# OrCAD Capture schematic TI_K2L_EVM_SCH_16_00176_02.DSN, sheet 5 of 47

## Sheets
5 PAGE29 : K2L_BMC: size C; title: BMC Processor (LM3S2D93), switches, DIPsw, UART Rx Mux, LEDs
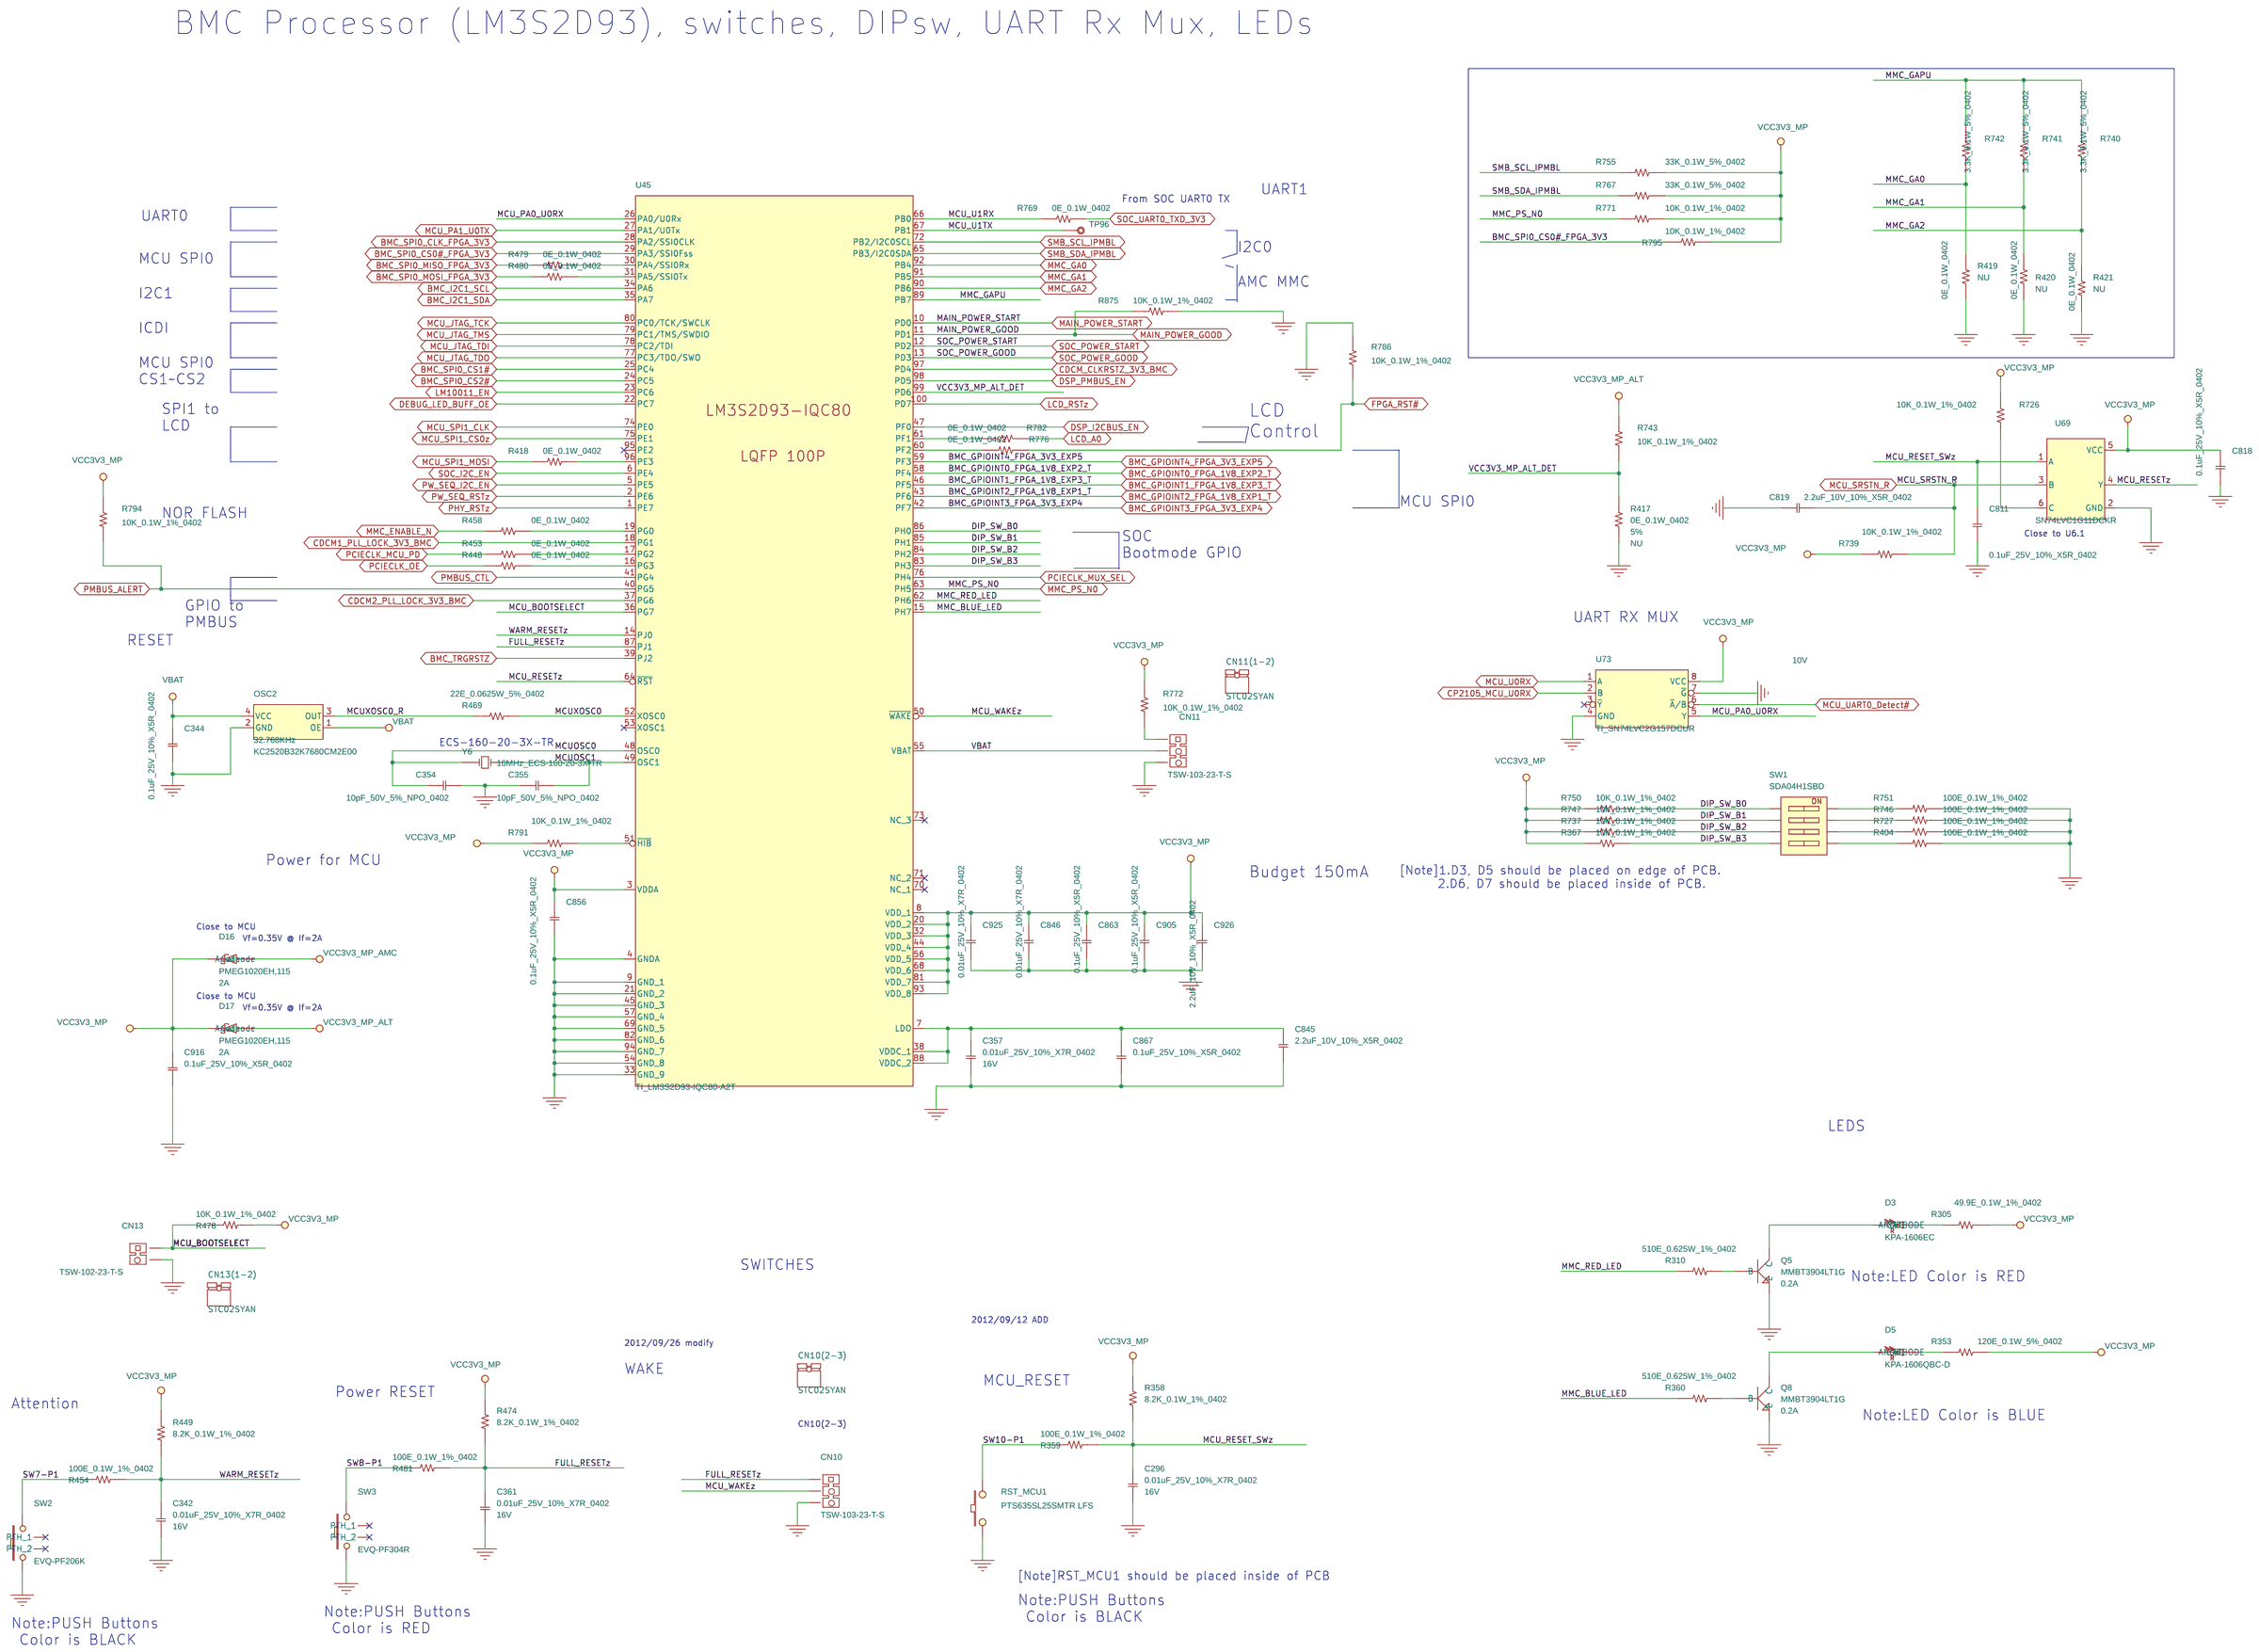
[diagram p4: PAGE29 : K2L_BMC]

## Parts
C296  0.01uF_25V_10%_X7R_0402  [C0402]
C342  0.01uF_25V_10%_X7R_0402  [C0402]
C344  0.1uF_25V_10%_X5R_0402  [C0402]
C354  10pF_50V_5%_NPO_0402  [C0402]
C355  10pF_50V_5%_NPO_0402  [C0402]
C357  0.01uF_25V_10%_X7R_0402  [C0402]
C361  0.01uF_25V_10%_X7R_0402  [C0402]
C811  0.1uF_25V_10%_X5R_0402  [C0402]
C818  0.1uF_25V_10%_X5R_0402  [C0402]
C819  2.2uF_10V_10%_X5R_0402  [C0402]
C845  2.2uF_10V_10%_X5R_0402  [C0402]
C846  0.01uF_25V_10%_X7R_0402  [C0402]
C856  0.1uF_25V_10%_X5R_0402  [C0402]
C863  0.1uF_25V_10%_X5R_0402  [C0402]
C867  0.1uF_25V_10%_X5R_0402  [C0402]
C905  0.1uF_25V_10%_X5R_0402  [C0402]
C916  0.1uF_25V_10%_X5R_0402  [C0402]
C925  0.01uF_25V_10%_X7R_0402  [C0402]
C926  2.2uF_10V_10%_X5R_0402  [C0402]
CN10  TSW-103-23-T-S  [BERG_1X3]
CN10(2-3)  STC02SYAN  [NA]
CN11  TSW-103-23-T-S  [BERG_1X3]
CN11(1-2)  STC02SYAN  [NA]
CN13  TSW-102-23-T-S  [SAMTSW-102-22-T-S]
CN13(1-2)  STC02SYAN  [NA]
D3  KPA-1606EC  [LED_2P_KPA-1606EC]
D5  KPA-1606QBC-D  [LED_2P_KPA-1606QBC-D]
D16  PMEG1020EH,115  [DIODE_2P_146_106x61_ANODE2]
D17  PMEG1020EH,115  [DIODE_2P_146_106x61_ANODE2]
OSC2  32.768KHz  [OSCCC200X250X70-4N]
Q5  MMBT3904LT1G  [SOT-23]
Q8  MMBT3904LT1G  [SOT-23]
R305  49.9E_0.1W_1%_0402  [R0402]
R310  510E_0.625W_1%_0402  [R0402]
R353  120E_0.1W_5%_0402  [R0402]
R358  8.2K_0.1W_1%_0402  [R0402]
R359  100E_0.1W_1%_0402  [R0402]
R360  510E_0.625W_1%_0402  [R0402]
R367  10K_0.1W_1%_0402  [R0402]
R404  100E_0.1W_1%_0402  [R0402]
R417  0E_0.1W_0402  [R0402]
R418  0E_0.1W_0402  [R0402]
R419  0E_0.1W_0402  [R0402]
R420  0E_0.1W_0402  [R0402]
R421  0E_0.1W_0402  [R0402]
R448  0E_0.1W_0402  [R0402]
R449  8.2K_0.1W_1%_0402  [R0402]
R453  0E_0.1W_0402  [R0402]
R454  100E_0.1W_1%_0402  [R0402]
R458  0E_0.1W_0402  [R0402]
R469  22E_0.0625W_5%_0402  [R0402]
R474  8.2K_0.1W_1%_0402  [R0402]
R478  10K_0.1W_1%_0402  [R0402]
R479  0E_0.1W_0402  [R0402]
R480  0E_0.1W_0402  [R0402]
R481  100E_0.1W_1%_0402  [R0402]
R726  10K_0.1W_1%_0402  [R0402]
R727  100E_0.1W_1%_0402  [R0402]
R737  10K_0.1W_1%_0402  [R0402]
R739  10K_0.1W_1%_0402  [R0402]
R740  3.3K_0.1W_5%_0402  [R0402]
R741  3.3K_0.1W_5%_0402  [R0402]
R742  3.3K_0.1W_5%_0402  [R0402]
R743  10K_0.1W_1%_0402  [R0402]
R746  100E_0.1W_1%_0402  [R0402]
R747  10K_0.1W_1%_0402  [R0402]
R750  10K_0.1W_1%_0402  [R0402]
R751  100E_0.1W_1%_0402  [R0402]
R755  33K_0.1W_5%_0402  [R0402]
R767  33K_0.1W_5%_0402  [R0402]
R769  0E_0.1W_0402  [R0402]
R771  10K_0.1W_1%_0402  [R0402]
R772  10K_0.1W_1%_0402  [R0402]
R776  0E_0.1W_0402  [R0402]
R782  0E_0.1W_0402  [R0402]
R786  10K_0.1W_1%_0402  [R0402]
R791  10K_0.1W_1%_0402  [R0402]
R794  10K_0.1W_1%_0402  [R0402]
R795  10K_0.1W_1%_0402  [R0402]
R875  10K_0.1W_1%_0402  [R0402]
RST_MCU1  PTS635SL25SMTR LFS  [SW_PTS635SL25SMTRLFS]
SW1  SDA04H1SBD  [SW_SDA04H1SBD]
SW2  EVQ-PF206K  [SW_EVQ-PF206K]
SW3  EVQ-PF304R  [SW_EVQ-PF104R]
TP96  TP  [TP-S40]
U45  TI_LM3S2D93-IQC80-A2T  [QFP_100P_20_630x630]
U69  SN74LVC1G11DCKR  [SC70_6p]
U73  TI_SN74LVC2G157DCUR  [SOIC_8P_20_79X122]
Y6  16MHz_ECS-160-20-3X-TR  [XTAL_ECS-120-20-3X-TR]

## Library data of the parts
C296 C342 C357 C846 C925 = 11_C_0: CAP CER 10000PF 25V 10% X7R 0402; Advansus_Part_Number: 11G232110312030; Characteristic: 16V; Distributor_name: DIGIKEY; Distributor_part_number: 445-1260-1-ND; EIC Part#: 03_00029_04; GROUP: CPU1; Manufacture: TDK Corporation; Manufacture Part Number: C1005X7R1E103K; Manufacture(English): TDK Corporation; Manufacture_Part_Number: C1005X7R1E103K; Manufacturer: TDK Corporation; Manufacturer_Part_No: C1005X7R1E103K; Mfg: TDK Corporation; Mfg Part#: 03_00029_04; Mfr_name: TDK Corporation; Mfr_part_number: C1005X7R1E103K; Package: 0402; Part_Number: 1121610790; Price @ 1: 0.10000; Price @ 10K: 0.00420; Price @ 1K: 0.00600; ProcessType: SMT; ROOM: CPU1; Tolerance: 10%; Vendor: DIGIKEY; Vendor_Part_No: 445-1260-1-ND; eI Part#: 03_00029_04
C344 C856 C863 C867 C905 = 11_C_0: CAP CER 0.1UF 25V 10% X5R 0402; Avalue_Part_Number: E1123510400H; Distributor_name: DIGIKEY; Distributor_part_number: 445-4964-1-ND; EIC Part#: 03_00470_02; MOUNTED: <MOUNTED>; Manufacture: TDK Corporation; Manufacture Part Number: C1005X5R1E104K050BC; Manufacture(English): TDK Corporation; Manufacture_Part_Number: GRM155R71C104KA88D; Manufacturer: TDK Corporation; Manufacturer_Part_No: C1005X5R1E104K050BC; Mfg: Murata Electronics North America; Mfg Part#: 03_00470_02; Mfr_name: TDK Corporation; Mfr_part_number: C1005X5R1E104K050BC; Package: 0402; Price @ 1: 0.10000; Price @ 1K: 0.00420; ProcessType: SMT; Tolerance: 10%; Vendor: DIGIKEY; Vendor Part#: 445-4964-1-ND; Vendor_Part_No: 445-4964-1-ND; eI Part#: 03_00470_02
C354 C355 = 11_C_0: CAP CER 10PF 50V 5% NPO 0402; Advansus_Part_Number: 11G232010004030; Characteristic: 50V; Distributor_name: DIGIKEY; Distributor_part_number: 490-5921-6-ND; EIC Part#: 03_00366_03; Manufacture: Murata; Manufacture Part Number: GRM1555C1H100JA01D; Manufacture(English): Murata; Manufacture_Part_Number: CC0402JRNPO9BN100; Manufacturer: Murata; Manufacturer_Part_No: GRM1555C1H100JA01D; Mfg: Yageo; Mfg Part#: 03_00366_03; Mfr_name: Murata; Mfr_part_number: GRM1555C1H100JA01D; Package: 0402; Part_Number: 1124410091; Price @ 1: 0.10000; Price @ 10K: 0.00227; Price @ 1K: 0.00324; ProcessType: SMT; Tolerance: 5%; Vendor: DIGIKEY; Vendor_Part_No: 490-5921-6-ND; eI Part#: 03_00366_03
C361 = 11_C_0: CAP CER 10000PF 25V 10% X7R 0402; Advansus_Part_Number: 11G232110312030; Characteristic: 16V; Distributor_name: DIGIKEY; Distributor_part_number: 445-1260-1-ND; EIC Part#: 03_00029_04; GROUP: CPU1; Manufacture: TDK Corporation; Manufacture Part Number: C1005X7R1E103K; Manufacture(English): TDK Corporation; Manufacture_Part_Number: C1005X7R1E103K; Manufacturer: TDK Corporation; Manufacturer_Part_No: C1005X7R1E103K; Mfg: TDK Corporation; Mfg Part#: 03_00029_04; Mfr_name: TDK Corporation; Mfr_part_number: C1005X7R1E103K; Package: 0402; Part_Number: 1121610790; Price @ 1: 0.10000; Price @ 10K: 0.00420; Price @ 1K: 0.00600; ProcessType: SMT; ROOM: CPU1; Tolerance: 10%; Vendor: DIGIKEY; Vendor Part#: 445-1260-1-ND; Vendor_Part_No: 445-1260-1-ND; eI Part#: 03_00029_04
C811 C916 = 11_C_0: CAP CER 0.1UF 25V 10% X5R 0402; Avalue_Part_Number: E1123510400H; Distributor_name: DIGIKEY; Distributor_part_number: 445-4964-1-ND; EIC Part#: 03_00470_02; Manufacture: TDK Corporation; Manufacture Part Number: C1005X5R1E104K050BC; Manufacture(English): TDK Corporation; Manufacture_Part_Number: GRM155R71C104KA88D; Manufacturer: TDK Corporation; Manufacturer_Part_No: C1005X5R1E104K050BC; Mfg: Murata Electronics North America; Mfg Part#: 03_00470_02; Mfr_name: TDK Corporation; Mfr_part_number: C1005X5R1E104K050BC; Package: 0402; Price @ 1: 0.10000; Price @ 1K: 0.00420; ProcessType: SMT; Tolerance: 10%; Vendor: DIGIKEY; Vendor Part#: 445-4964-1-ND; Vendor_Part_No: 445-4964-1-ND; eI Part#: 03_00470_02
C818 = 11_C_12: CAP CER 0.1UF 25V 10% X5R 0402; Alt Mfg: Taiyo Yuden; Distributor_name: DIGIKEY; Distributor_part_number: 445-4964-1-ND; EIC Part#: 03_00470_02; Manufacture: TDK Corporation; Manufacture Part Number: C1005X5R1E104K050BC; Manufacture(English): TDK Corporation; Manufacture_Part_Number: GRM155R61E104KA87D; Manufacturer: TDK Corporation; Manufacturer_Part_No: C1005X5R1E104K050BC; Mfg: Murata Electronics North America; Mfg Part#: 03_00470_02; Mfr_name: TDK Corporation; Mfr_part_number: C1005X5R1E104K050BC; Oper. Temp. Range: -55°C ~ 85°C; Package: 0402; Price @ 1: 0.10000; Price @ 1K: 0.00960; ProcessType: SMT; RoHS: Yes; Tolerance: 10%; Vendor: DIGIKEY; Vendor Part#: 445-4964-1-ND; Vendor_Part_No: 445-4964-1-ND; eI Part#: 03_00470_02
C819 C845 C926 = Cap_Ceramic: CAP CER 2.2UF 10V 10% X5R 0402; Characteristic: <Characteristic>; Distributor_name: DIGIKEY; Distributor_part_number: 445-7392-1-ND; EIC Part#: 03_00055_05; Manufacture: TDK Corporation; Manufacture Part Number: C1005X5R1A225K050BC; Manufacture(English): TDK Corporation; Manufacture_Part_Number: C1005X5R1A225K050BC; Manufacturer: TDK Corporation; Manufacturer_Part_No: C1005X5R1A225K050BC; Mfg: TDK Corporation; Mfg Part#: C1005X5R1A225K050BC; Mfr_name: TDK Corporation; Mfr_part_number: C1005X5R1A225K050BC; Oper. Temp. Range: -55C to 105C; Package: 0402; ProcessType: SMT; RoHS: Yes; Tolerance: 10%; Vendor: DIGIKEY; Vendor Part#: 445-7392-1-ND; Vendor_Part_No: 445-7392-1-ND; Voltage: 10V; eI Part#: 03_00055_05
CN10 CN11 = 1653_JH3X1V-2M_0: CONN HEADER 3POS .100 SNGL TIN; Advansus_Part_Number: 12G060100033; Distributor_name: DIGIKEY; Distributor_part_number: SAM1075-03-ND; EIC Part#: 09_00962_01; Manufacture: Samtec Inc; Manufacture(English): Samtec Inc; Manufacturer: Samtec Inc; Mfg: Samtec; Mfg Part#: TBD; Mfr_name: Samtec Inc; Package: PH3x1P-2.00; Part_Number: 1653003101; Price @ 1: 0.53000; Price @ 10K: 0.23098; Price @ 1K: 0.26331; ProcessType: DIP; Vendor: DIGIKEY; Vendor_Part_No: SAM1075-03-ND; eI Part#: 09_00962_01
CN10(2-3) CN11(1-2) CN13(1-2) = 1653_MINIJUMPER22.0MM_0: CONN JUMPER SHORTING TIN; Distributor_name: DIGIKEY; Distributor_part_number: S9000-ND; EIC Part#: 09_00190_01; Manufacture: Sullins Connector; Manufacture(English): Sullins Connector; Manufacturer: Sullins Connector; Mfg: Sullins Connector Solutions; Mfg Part#: 09_00190_01; Mfr_name: Sullins Connector; Package: MINIJUMPER2P-2.00; Part_Number: 1653302122; Price @ 1: 0.29000; Price @ 10K: 0.04800; Price @ 1K: 0.06080; ProcessType: DIP; Vendor: DIGIKEY; Vendor_Part_No: S9000-ND; eI Part#: 09_00190_01
CN13 = 1653_HD_2P_D_0: CONN HEADER 2POS .100 SNGL TIN; AVL_Part: AVL; Advansus_Part_Number: 12G06010002DAD; Avalue_Part_Number: E1653002101R; Distributor_name: DIGIKEY; Distributor_part_number: SAM1075-02-ND; EIC Part#: 09_00957_01; Manufacture: Samtec Inc; Manufacture(English): Samtec Inc; Manufacturer: Samtec Inc; Mfg: Samtec Inc; Mfg Part#: 09_00957_01; Mfr_name: Samtec Inc; Package: PH2x1P-2.00; Part_Number: 1653002101-03; Price @ 1: 0.49000; Price @ 10K: 0.21284; Price @ 1K: 0.24263; ProcessType: DIP; Vendor: DIGIKEY; Vendor_Part_No: SAM1075-02-ND; eI Part#: TBD
D3 = 130_LED_2P_R_KPA-1606EC_0: LED RED SMD 1.6x0.6mm KPA-1606EC; AVL_Part: AVL; Distributor_name: ELEMENT14; Distributor_part_number: 2290355; EIC Part#: 06_00464_01; Manufacture: Kingbright Corporation; Manufacture(English): Kingbright Corporation; Manufacturer: Kingbright Corporation; Mfg: Kingbright Corporation; Mfg Part#: 06_00464_01; Mfr_name: Kingbright Corporation; Package: 1.6x0.6mm; Part_Number: 1304002687; Price @ 1: 0.19757; Price @ 1K: 0.15384; ProcessType: SMT; Vendor: ELEMENT14; Vendor_Part_No: 2290355; eI Part#: 06_00464_01
D5 = 130_LED_2P_B_KPA-1606QBC-D_2: LED Blue SMD 1.6x0.6mm KPA-1606QBC-D 90D; AVL_Part: AVL; Distributor_name: ELEMENT14; Distributor_part_number: 2290362; EIC Part#: TBD; Manufacture: Kingbright Corporation; Manufacture(English): Kingbright Corporation; Manufacturer: Kingbright Corporation; Mfg: Kingbright Corporation; Mfg Part#: TBD; Mfr_name: Kingbright Corporation; Package: 1.6x0.6mm; Part_Number: 1304003126; Price @ 1: 0.31000; Price @ 1K: 0.24100; ProcessType: SMT; Vendor: ELEMENT14; Vendor_Part_No: 2290362; eI Part#: TBD
D16 D17 = 130_SCHOTTKY_ANODE2_0: DIODE SCHOTTKY 10V 2A SOD123F; AVL_Part: AVL; Characteristic: 2A; Distributor_name: DIGIKEY; Distributor_part_number: 568-4105-1-ND; EIC Part#: 06_00466_01; Manufacture: NXP Semiconductors; Manufacture(English): NXP Semiconductors; Manufacturer: NXP Semiconductors; Mfg: NXP Semiconductors; Mfg Part#: 06_00466_01; Mfr_name: NXP Semiconductors; Package: SOD-123; Part_Number: 1300003967; Price @ 1: 0.43000; Price @ 10K: 0.10676; Price @ 1K: 0.11970; ProcessType: SMT; Vendor: DIGIKEY; Vendor_Part_No: 568-4105-1-ND; eI Part#: 06_00466_01
OSC2 = 1233_OSC_4P_0: OSCILLATOR 32.768KHZ 3.3V SMD; Characteristic: KC2520B32K7680CM2E00; Distributor_name: DIGIKEY; Distributor_part_number: 1253-1026-1-ND; EIC Part#: 08_00173_01; Manufacture: AVX Corp/Kyocera Corp; Manufacture Part Number: KC2520B32K7680CM2E00; Manufacture(English): AVX Corp/Kyocera Corp; Manufacture_Part_Number: KC2520B32K7680CM2E00; Manufacturer: AVX Corp/Kyocera Corp; Manufacturer_Part_No: KC2520B32K7680CM2E00; Mfg: AVX Corp/Kyocera Corp; Mfg Part#: 08_00173_01; Mfr_name: AVX Corp/Kyocera Corp; Mfr_part_number: KC2520B32K7680CM2E00; Oper. Temp. Range: -40C to 85C; Package: 4-SMD; Part_Number: KC2520B32K7680CM2E00; Price @ 1: 3.00000; Price @ 10K: 1.12000; Price @ 1K: 1.20000; ProcessType: SMT; RoHS: Yes; Vendor: DIGIKEY; Vendor Part#: 1253-1026-2-ND; Vendor_Part_No: 1253-1026-1-ND; eI Part#: 08_00173_01
Q5 Q8 = 131_SOT-23A_BEC_0: TRANS GP SS NPN 40V SOT23; Characteristic: 0.2A; Distributor_name: DIGIKEY; Distributor_part_number: MMBT3904LT3GOSCT-ND; EIC Part#: 07_00016_03; Manufacture: ON Semiconductor; Manufacture(English): ON Semiconductor; Manufacturer: ON Semiconductor; Mfg: ON Semiconductors; Mfg Part#: 07_00016_03; Mfr_name: ON Semiconductor; Part_Number: 1310390410-03; Price @ 1: 0.11000; Price @ 10K: 0.01420; Price @ 1K: 0.02194; ProcessType: SMT; Vendor: DIGIKEY; Vendor_Part_No: MMBT3904LT3GOSCT-ND; eI Part#: 07_00016_03
R305 = 10_R_0: RES 49.9 OHM 1/10W 1% 0402 SMD; Alt Mfg: Yageo; Alt Mfg Part#: RC0402FR-0749R9L; Distributor_name: DIGIKEY; Distributor_part_number: P49.9LCT-ND; EIC Part#: 02_00025_01; Manufacture: Panasonic - ECG; Manufacture Part Number: ERJ-2RKF49R9X; Manufacture(English): Panasonic - ECG; Manufacture_Part_Number: ERJ-2RKF49R9X; Manufacturer: Panasonic - ECG; Manufacturer_Part_No: ERJ-2RKF49R9X; Mfg: Panasonic - ECG; Mfg Part#: ERJ-2RKF49R9X; Mfr_name: Panasonic - ECG; Mfr_part_number: ERJ-2RKF49R9X; Oper. Temp. Range: -55C to 125C; Package: 0402; Price @ 1: 0.10000; Price @ 1K: 0.00672; ProcessType: SMT; RoHS: Yes; Tolerance: 1%; Vendor: DIGIKEY; Vendor Part#: P49.9LCT-ND; Vendor_Part_No: P49.9LCT-ND; eI Part#: 02_00025_01
R310 R360 = 10_R_0: RES 510 OHM 1/16W 1% 0402 SMD; AVL_Part: AVL; Advansus_Part_Number: 10G212510014010; Avalue_Part_Number: E1050505110H; Characteristic: 1%; Distributor_name: DIGIKEY; Distributor_part_number: 541-510LCT-ND; EIC Part#: 02_00958_01; Manufacture: Vishay Dale; Manufacture Part Number: CRCW0402510RFKED; Manufacture(English): Vishay Dale; Manufacture_Part_Number: CRCW0402510RFKED; Manufacturer: Vishay Dale; Manufacturer_Part_No: CRCW0402510RFKED; Mfg: Vishay Dale; Mfg Part#: CRCW0402510RFKED; Mfr_name: Vishay Dale; Mfr_part_number: CRCW0402510RFKED; Package: 0402; Part_Number: 1000003471-04; Price @ 1: 0.10000; Price @ 10K: 0.00347; Price @ 1K: 0.00672; ProcessType: SMT; Tolerance: 1%; Vendor: DigiKey; Vendor_Part_No: 541-510LCT-ND; eI Part#: 02_00958_01
R353 = 10_R_0: RES 120 OHM 1/10W 5% 0402 SMD; Distributor_name: DIGIKEY; Distributor_part_number: P120JCT-ND; EIC Part#: TBD; Manufacture: Panasonic - ECG; Manufacture Part Number: ERJ-2GEJ121X; Manufacture(English): Panasonic - ECG; Manufacture_Part_Number: ERJ-2GEJ121X; Manufacturer: Panasonic - ECG; Manufacturer_Part_No: ERJ-2GEJ121X; Mfg Part#: TBD; Mfr_name: Panasonic - ECG; Mfr_part_number: ERJ-2GEJ121X; Price @ 1: 0.10000; Price @ 10K: 0.00248; Price @ 1K: 0.00480; Vendor: DIGIKEY; Vendor_Part_No: P120JCT-ND; eI Part#: 02_00348_01
R358 = 10_R_0: RES 8.2K OHM 1/10W 1% 0402 SMD; Characteristic: 5%; Distributor_name: DIGIKEY; Distributor_part_number: P8.20KLCT-ND; EIC Part#: 02_00061_02; Manufacture: Panasonic - ECG; Manufacture Part Number: ERJ-2RKF8201X; Manufacture(English): Panasonic - ECG; Manufacture_Part_Number: ERJ-2RKF8201X; Manufacturer: Panasonic - ECG; Manufacturer_Part_No: ERJ-2RKF8201X; Mfg: Panasonic Electronic Components; Mfg Part#: 02_00061_02; Mfr_name: Panasonic - ECG; Mfr_part_number: ERJ-2RKF8201X; Package: 0402; Part_Number: 105A782024; Price @ 1: 0.10000; Price @ 10K: 0.00347; Price @ 1K: 0.00672; ProcessType: SMT; Tolerance: 5%; Vendor: DIGIKEY; Vendor_Part_No: P8.20KLCT-ND; eI Part#: 02_00424_01
R359 R481 = 10_R_0: RES 100 OHM 1/10W 1% 0402 SMD; Characteristic: 1%; Distributor_name: DIGIKEY; Distributor_part_number: P100LCT-ND; EIC Part#: 02_00043_02; Manufacture: Panasonic - ECG; Manufacture Part Number: ERJ-2RKF1000X; Manufacture(English): Panasonic - ECG; Manufacture_Part_Number: ERJ-2RKF1000X; Manufacturer: Panasonic - ECG; Manufacturer_Part_No: ERJ-2RKF1000X; Mfg: Panasonic Electronic Components; Mfg Part#: 02_00043_02; Mfr_name: Panasonic - ECG; Mfr_part_number: ERJ-2RKF1000X; Package: 0402; Part_Number: 105A510004; Price @ 1: 0.10000; Price @ 10K: 0.00347; Price @ 1K: 0.00672; ProcessType: SMT; Tolerance: 1%; Vendor: DIGIKEY; Vendor_Part_No: P100LCT-ND; eI Part#: 02_00019_01
R367 R478 R726 R737 R739 R743 R747 R750 R771 R772 R786 R791 R794 R795 = 10_R_0: RES 10K OHM 1/10W 1% 0402 SMD; Characteristic: 1%; Distributor_name: DIGIKEY; Distributor_part_number: P10.0KLCT-ND; EIC Part#: 02_00027_01; MOUNTED: <MOUNTED>; Manufacture: Panasonic - ECG; Manufacture Part Number: ERJ-2RKF1002X; Manufacture(English): Panasonic - ECG; Manufacture_Part_Number: ERJ-2RKF1002X; Manufacturer: Panasonic - ECG; Manufacturer_Part_No: ERJ-2RKF1002X; Mfg: PANASONIC ELECTRONIC COMPONENTS (VA); Mfg Part#: 02_00027_01; Mfr_name: Panasonic - ECG; Mfr_part_number: ERJ-2RKF1002X; Package: 0402; Part_Number: 105A50103A; Price @ 1: 0.10000; Price @ 10K: 0.00347; Price @ 1K: 0.00672; ProcessType: SMT; Tolerance: 1%; Vendor: DIGIKEY; Vendor_Part_No: P10.0KLCT-ND; eI Part#: 02_00027_01
R404 = 10_R_0: RES 100 OHM 1/10W 1% 0402 SMD; Characteristic: 1%; Distributor_name: DIGIKEY; Distributor_part_number: P100LCT-ND; EIC Part#: 02_00043_02; Manufacture: Panasonic - ECG; Manufacture Part Number: ERJ-2RKF1000X; Manufacture(English): Panasonic - ECG; Manufacture_Part_Number: ERJ-2RKF1000X; Manufacturer: Panasonic - ECG; Manufacturer_Part_No: ERJ-2RKF1000X; Mfg: Panasonic Electronic Components; Mfg Part#: 02_00043_02; Mfr_name: Panasonic - ECG; Mfr_part_number: ERJ-2RKF1000X; Package: 0402; Part_Number: 105A510004; Price @ 1: 0.10000; Price @ 10K: 0.00347; Price @ 1K: 0.00672; ProcessType: SMT; Tolerance: 1%; Vendor: DIGIKEY; Vendor_Part_No: P100LCT-ND; eI Part#: 02_00027_01
R417 R419-R421 = 10_R_0: RES 0.0 OHM 1/10W JUMP 0402 SMD; Characteristic: 5%; Distributor_name: DIGIKEY; Distributor_part_number: P0.0JCT-ND; EIC Part#: 02_00019_01; Manufacture: Panasonic - ECG; Manufacture Part Number: ERJ-2GE0R00X; Manufacture(English): Panasonic - ECG; Manufacture_Part_Number: ERJ-2GE0R00X; Manufacturer: Panasonic - ECG; Manufacturer_Part_No: ERJ-2GE0R00X; Mfg: Panasonic Electronic Components; Mfg Part#: 02_00019_01; Mfr_name: Panasonic - ECG; Mfr_part_number: ERJ-2GE0R00X; Mounting Status: NU; Mounting_Status: NU; Package: 0402; Part_Number: 105A700004-02; Price @ 1: 0.05000; Price @ 10K: 0.00248; Price @ 1K: 0.00480; ProcessType: SMT; Tolerance: 5%; Vendor: DIGIKEY; Vendor_Part_No: P0.0JCT-ND; eI Part#: 02_00019_01
R418 R448 R453 R458 R479 R480 R769 R776 R782 = 10_R_0: RES 0.0 OHM 1/10W JUMP 0402 SMD; Characteristic: 5%; Distributor_name: DIGIKEY; Distributor_part_number: P0.0JCT-ND; EIC Part#: 02_00019_01; Manufacture: Panasonic - ECG; Manufacture Part Number: ERJ-2GE0R00X; Manufacture(English): Panasonic - ECG; Manufacture_Part_Number: ERJ-2GE0R00X; Manufacturer: Panasonic - ECG; Manufacturer_Part_No: ERJ-2GE0R00X; Mfg: Panasonic Electronic Components; Mfg Part#: 02_00019_01; Mfr_name: Panasonic - ECG; Mfr_part_number: ERJ-2GE0R00X; Package: 0402; Part_Number: 105A700004; Price @ 1: 0.05000; Price @ 10K: 0.00248; Price @ 1K: 0.00480; ProcessType: SMT; Tolerance: 5%; Vendor: DIGIKEY; Vendor_Part_No: P0.0JCT-ND; eI Part#: 02_00019_01
R449 R474 = 10_R_0: RES 8.2K OHM 1/10W 1% 0402 SMD; Characteristic: 5%; Distributor_name: DIGIKEY; Distributor_part_number: P8.20KLCT-ND; EIC Part#: 02_00061_02; Manufacture: Panasonic - ECG; Manufacture Part Number: ERJ-2RKF8201X; Manufacture(English): Panasonic - ECG; Manufacture_Part_Number: ERJ-2RKF8201X; Manufacturer: Panasonic - ECG; Manufacturer_Part_No: ERJ-2RKF8201X; Mfg: Panasonic Electronic Components; Mfg Part#: 02_00061_02; Mfr_name: Panasonic - ECG; Mfr_part_number: ERJ-2RKF8201X; Package: 0402; Part_Number: 105A782024; Price @ 1: 0.10000; Price @ 10K: 0.00347; Price @ 1K: 0.00672; ProcessType: SMT; Tolerance: 5%; Vendor: DIGIKEY; Vendor_Part_No: P8.20KLCT-ND; eI Part#: 02_00019_01
R454 = 10_R_0: RES 100 OHM 1/10W 1% 0402 SMD; Characteristic: 1%; Distributor_name: DIGIKEY; Distributor_part_number: P100LCT-ND; EIC Part#: 02_00043_02; Manufacture: Panasonic - ECG; Manufacture Part Number: ERJ-2RKF1000X; Manufacture(English): Panasonic - ECG; Manufacture_Part_Number: ERJ-2RKF1000X; Manufacturer: Panasonic - ECG; Manufacturer_Part_No: ERJ-2RKF1000X; Mfg: Panasonic Electronic Components; Mfg Part#: 02_00043_02; Mfr_name: Panasonic - ECG; Mfr_part_number: ERJ-2RKF1000X; Package: 0402; Part_Number: 105A510004; Price @ 1: 0.10000; Price @ 10K: 0.00347; Price @ 1K: 0.00672; ProcessType: SMT; Tolerance: 1%; Vendor: DIGIKEY; Vendor_Part_No: P100LCT-ND; eI Part#: 02_00024_01
R469 = 10_R_0: RES 22 OHM 1/16W 1% 0402 SMD; Characteristic: 5%; Distributor_name: DIGIKEY; Distributor_part_number: P22JCT-ND; EIC Part#: 02_00233_01; MOUNTED: <MOUNTED>; Manufacture: Panasonic - ECG; Manufacture Part Number: ERJ-2GEJ220X; Manufacture(English): Panasonic - ECG; Manufacture_Part_Number: ERJ-2GEJ220X; Manufacturer: Panasonic - ECG; Manufacturer_Part_No: ERJ-2GEJ220X; Mfg: Panasonic - ECG; Mfg Part#: ERJ-2GEJ220X; Mfr_name: Panasonic - ECG; Mfr_part_number: ERJ-2GEJ220X; Package: 0402; Part_Number: 105A722064; Price @ 1: 0.10000; Price @ 10K: 0.00132; Price @ 1K: 0.00233; ProcessType: SMT; Tolerance: 5%; Vendor: DIGIKEY; Vendor Part#: P22JCT-ND; Vendor_Part_No: P22JCT-ND; eI Part#: 02_00233_01
R727 R746 R751 = 10_R_0: RES 100 OHM 1/10W 1% 0402 SMD; Characteristic: 1%; Distributor_name: DIGIKEY; Distributor_part_number: P100LCT-ND; EIC Part#: 02_00043_02; Manufacture: Panasonic - ECG; Manufacture Part Number: ERJ-2RKF1000X; Manufacture(English): Panasonic - ECG; Manufacture_Part_Number: ERJ-2RKF1000X; Manufacturer: Panasonic - ECG; Manufacturer_Part_No: ERJ-2RKF1000X; Mfg: Panasonic Electronic Components; Mfg Part#: 02_00043_02; Mfr_name: Panasonic - ECG; Mfr_part_number: ERJ-2RKF1000X; Package: 0402; Part_Number: 105A510004; Price @ 1: 0.10000; Price @ 10K: 0.00347; Price @ 1K: 0.00672; ProcessType: SMT; Tolerance: 1%; Vendor: DIGIKEY; Vendor_Part_No: P100LCT-ND; eI Part#: 02_00355_01
R740 R742 = 10_R_0: RES 3.3K OHM 1/10W 5% 0402 SMD; Characteristic: 5%; Distributor_name: DIGIKEY; Distributor_part_number: P3.3KJCT-ND; EIC Part#: 02_00355_01; Manufacture: Panasonic - ECG; Manufacture Part Number: ERJ-2GEJ332X; Manufacture(English): Panasonic - ECG; Manufacture_Part_Number: ERJ-2GEJ332X; Manufacturer: Panasonic - ECG; Manufacturer_Part_No: ERJ-2GEJ332X; Mfg: Panasonic Electronic Components; Mfg Part#: 02_00355_01; Mfr_name: Panasonic - ECG; Mfr_part_number: ERJ-2GEJ332X; Package: 0402; Part_Number: 105A73301A-01; Price @ 1: 0.10000; Price @ 10K: 0.00248; Price @ 1K: 0.00480; ProcessType: SMT; Tolerance: 5%; Vendor: DIGIKEY; Vendor_Part_No: P3.3KJCT-ND; eI Part#: 02_00266_01
R741 = 10_R_0: RES 3.3K OHM 1/10W 5% 0402 SMD; Characteristic: 5%; Distributor_name: DIGIKEY; Distributor_part_number: P3.3KJCT-ND; EIC Part#: 02_00355_01; Manufacture: Panasonic - ECG; Manufacture Part Number: ERJ-2GEJ332X; Manufacture(English): Panasonic - ECG; Manufacture_Part_Number: ERJ-2GEJ332X; Manufacturer: Panasonic - ECG; Manufacturer_Part_No: ERJ-2GEJ332X; Mfg: Panasonic Electronic Components; Mfg Part#: 02_00355_01; Mfr_name: Panasonic - ECG; Mfr_part_number: ERJ-2GEJ332X; Package: 0402; Part_Number: 105A73301A-01; Price @ 1: 0.10000; Price @ 10K: 0.00248; Price @ 1K: 0.00480; ProcessType: SMT; Tolerance: 5%; Vendor: DIGIKEY; Vendor_Part_No: P3.3KJCT-ND; eI Part#: 02_00356_01
R755 R767 = 10_R_0: RES 33K OHM 1/10W 5% 0402 SMD; Characteristic: 5%; Distributor_name: DIGIKEY; Distributor_part_number: P33KJCT-ND; EIC Part#: 02_00356_01; Manufacture: Panasonic - ECG; Manufacture Part Number: ERJ-2GEJ333X; Manufacture(English): Panasonic - ECG; Manufacture_Part_Number: ERJ-2GEJ333X; Manufacturer: Panasonic - ECG; Manufacturer_Part_No: ERJ-2GEJ333X; Mfg: Panasonic Electronic Components; Mfg Part#: 02_00356_01; Mfr_name: Panasonic - ECG; Mfr_part_number: ERJ-2GEJ333X; Package: 0402; Part_Number: 1000000830; Price @ 1: 0.10000; Price @ 10K: 0.00248; Price @ 1K: 0.00480; ProcessType: SMT; Tolerance: 5%; Vendor: DIGIKEY; Vendor_Part_No: P33KJCT-ND; eI Part#: 02_00348_01
R875 = 10_R_0: RES 10K OHM 1/10W 1% 0402 SMD; Characteristic: 1%; Distributor_name: DIGIKEY; Distributor_part_number: P10.0KLCT-ND; EIC Part#: 02_00027_01; Manufacture: Panasonic - ECG; Manufacture Part Number: ERJ-2RKF1002X; Manufacture(English): Panasonic - ECG; Manufacture_Part_Number: ERJ-2RKF1002X; Manufacturer: Panasonic - ECG; Manufacturer_Part_No: ERJ-2RKF1002X; Mfg: PANASONIC ELECTRONIC COMPONENTS (VA); Mfg Part#: 02_00027_01; Mfr_name: Panasonic - ECG; Mfr_part_number: ERJ-2RKF1002X; Package: 0402; Part_Number: 105A50103A; Price @ 1: 0.10000; Price @ 10K: 0.00347; Price @ 1K: 0.00672; ProcessType: SMT; Tolerance: 1%; Vendor: DIGIKEY; Vendor_Part_No: P10.0KLCT-ND; eI Part#: 02_00027_01
RST_MCU1 = 160_SW_2P_PT-004-E1_0: SWITCH TACTILE SPST-NO 0.05A 12V; Distributor_name: DIGIKEY; Distributor_part_number: CKN9119CT-ND; EIC Part#: TBD; Manufacture: C&K Components; Manufacture(English): C&K Components; Manufacturer: C&K Components; Mfg: C&K Components; Mfg Part#: TBD; Mfr_name: C&K Components; Price @ 1: 0.71000; Price @ 10K: 0.30150; Price @ 1K: 0.36482; ProcessType: SMT; Vendor: DIGIKEY; Vendor_Part_No: CKN9119CT-ND; eI Part#: NA
SW1 = 160_SW_8P_ESD104EZ_0: SWITCH DIP TOP SLIDE 4POS SMD; Distributor_name: DIGIKEY; Distributor_part_number: CKN6068-ND; EIC Part#: TBD; Manufacture: C&K Components; Manufacture(English): C&K Components; Manufacturer: C&K Components; Mfg: C&K Components; Mfg Part#: TBD; Mfr_name: C&K Components; Package: DIPSW*4SMD; Part_Number: 1600002430; Price @ 1: 1.74000; Price @ 10K: 0.93940; Price @ 1K: 1.07360; ProcessType: SMT; Vendor: DIGIKEY; Vendor_Part_No: CKN6068-ND; eI Part#: NA
SW2 = 160_SW-HDK632_2: SWITCH TACTILE SPST-NO 0.02A 15V; Distributor_name: DigiKey; Distributor_part_number: P12210S-ND; EIC Part#: 11_00114_01; Manufacture: Panasonic - ECG; Manufacture(English): Panasonic - ECG; Manufacturer: Panasonic - ECG; Mfg: Panasonic - ECG; Mfg Part#: 11_00114_01; Mfr_name: Panasonic - ECG; Package: SW2PDIP; ProcessType: DIP; RoHS: Yes; Vendor: DigiKey; Vendor Part#: P12210S-ND; Vendor_Part_No: P12210S-ND; eI Part#: 11_00114_01
SW3 = 160_SW-HDK632_0: SWITCH TACTILE SPST-NO 0.02A 15V; Distributor_name: DigiKey; Distributor_part_number: P12213S-ND; EIC Part#: 11_00115_01; Manufacture: Panasonic - ECG; Manufacture(English): Panasonic - ECG; Manufacturer: Panasonic - ECG; Mfg: Panasonic - ECG; Mfg Part#: 11_00115_01; Mfr_name: Panasonic - ECG; Package: SW2PDIP; ProcessType: DIP; RoHS: Yes; Vendor: DigiKey; Vendor Part#: P12213S-ND; Vendor_Part_No: P12213S-ND; eI Part#: 11_00115_01
TP96 = 00_TP28_0: TEST PAD TP; Advansus_Part_Number: 0030000003; Avalue_Part_Number: 0030000003; Distributor_name: NA; Distributor_part_number: NA; EIC Part#: NA; Manufacture: NA; Manufacture Part Number: NA; Manufacture(English): NA; Manufacture_Part_Number: NA; Manufacturer: NA; Manufacturer_Part_No: NA; Mfg: NA; Mfg Part#: NA; Mfr_name: NA; Mfr_part_number: NA; Part_Number: 0030000003; Price @ 1: NA; Price @ 10K: NA; Price @ 1K: NA; ProcessType: SMT; Vendor: NA; Vendor_Part_No: NA; eI Part#: NA
U45 = 14_TI_LM3S2D93-IQC80_2: IC MCU 32BIT 512KB FLASH 100LQFP; Distributor_name: DIGIKEY; Distributor_part_number: LM3S2D93-IQC80-A2T-ND; EIC Part#: 01_01116_01; Manufacture: TI; Manufacture Part Number: LM3S2D93-IQC80-A2T; Manufacture(English): TI; Manufacture_Part_Number: LM3S2D93-IQC80-A2T; Manufacturer: TI; Manufacturer_Part_No: LM3S2D93-IQC80-A2T; Mfg: TI; Mfg Part#: 01_01116_01; Mfr_name: TI; Mfr_part_number: LM3S2D93-IQC80-A2T; Package: LQFP100; Part_Number: 1400004661-01; Price @ 1: 16.74256; Price @ 1K: 12.10300; ProcessType: SMT; Vendor: DIGIKEY; Vendor_Part_No: LM3S2D93-IQC80-A2T-ND; eI Part#: 01_01125_01
U69 = SN74LVC1G11DCKR: IC SNGL 3IN POS AND GATE SC70-6; Distributor_name: DIGIKEY; Distributor_part_number: 296-18066-1-ND; EIC Part#: 01_00049_01; Manufacture: TI; Manufacture(English): TI; Manufacturer: TI; Mfg: TI; Mfg Part#: 01_00049_01; Mfr_name: TI; Package: SOT-363; Price @ 1: 0.40000; Price @ 10K: 0.09900; Price @ 1K: 0.11100; RoHS: Yes; Vendor: DIGIKEY; Vendor Part#: 296-18066-1-ND; Vendor_Part_No: 296-18066-1-ND; eI Part#: 01_01125_01
U73 = 141_TI_SN74LVC2G157_0: IC MULTIPLEXER DATA SEL US8; Distributor_name: DIGIKEY; Distributor_part_number: 296-12605-1-ND; EIC Part#: 01_01117_01; Manufacture: TI; Manufacture Part Number: SN74LVC2G157DCUR; Manufacture(English): TI; Manufacture_Part_Number: SN74LVC2G157DCUR; Manufacturer: TI; Manufacturer_Part_No: SN74LVC2G157DCUR; Mfg: TI; Mfg Part#: 01_01117_01; Mfr_name: TI; Mfr_part_number: SN74LVC2G157DCUR; Package: VSSOP8; Part_Number: 1410023116-01; Price @ 1: 0.70000; Price @ 10K: 0.24650; Price @ 1K: 0.28050; ProcessType: SMT; Vendor: DIGIKEY; Vendor_Part_No: 296-12605-1-ND; eI Part#: TBD
Y6 = 1231_XTAL_2P_0: CRYSTAL 16MHZ 20PF SMD; Distributor_name: DIGIKEY; Distributor_part_number: XC1776CT-ND; EIC Part#: 08_00172_01; Manufacture: ECS Inc; Manufacture Part Number: ECS-160-20-3X-TR; Manufacture(English): ECS Inc; Manufacture_Part_Number: ECS-160-20-3X-TR; Manufacturer: ECS Inc; Manufacturer_Part_No: ECS-160-20-3X-TR; Mfg: ECS Inc; Mfg Part#: 08_00172_01; Mfr_name: ECS Inc; Mfr_part_number: ECS-160-20-3X-TR; Package: XTAL5*3.2mm; Part_Number: 1231000343; Price @ 1: 0.53000; Price @ 10K: 0.18900; Price @ 1K: 0.21000; ProcessType: SMT; Tolerance: 20ppm; Vendor: DIGIKEY; Vendor_Part_No: XC1776CT-ND; eI Part#: 08_00172_01

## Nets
GND: C296.2 C342.2 C344.1 C354.2 C355.1 C357.2 C361.2 C811.2 C818.2 C819.1 C845.1 C846.2 C856.1 C863.1 C867.1 C905.1 C916.2 C925.2 C926.2 CN10.3 CN11.3 CN13.2 OSC2.2(GND) Q5.2(E) Q8.2(E) R404.1 R417.2 R419.2 R420.2 R421.2 R727.1 R746.1 R751.1 R786.2 R875.1 RST_MCU1.1 SW2.2 SW3.2 U45.4(GNDA) U45.9(GND_1) U45.21(GND_2) U45.33(GND_9) U45.45(GND_3) U45.54(GND_8) U45.57(GND_4) U45.69(GND_5) U45.82(GND_6) U45.94(GND_7) U69.2(GND) U73.4(GND) U73.7(~{G}) ; also on sheet 1 2 3 4 6 8 10 11 12 13 14 15 16 17 18 19 20 21 22 24 25 26 27 28 29 33 34 35 36 37 40 41 42 43 45 46 47
VBAT: C344.2 CN11.2 OSC2.1(OE) OSC2.4(VCC) U45.55(VBAT)
VCC3V3_MP: C818.1 C846.1 C856.2 C863.2 C905.2 C916.1 C925.1 C926.1 D16.1(Cathode) D17.1(Cathode) R305.2 R353.2 R358.2 R367.2 R449.2 R474.2 R478.2 R726.2 R737.2 R739.1 R747.2 R750.2 R755.2 R767.2 R771.1 R772.2 R791.1 R794.2 R795.1 U45.3(VDDA) U45.8(VDD_1) U45.20(VDD_2) U45.32(VDD_3) U45.44(VDD_4) U45.56(VDD_5) U45.68(VDD_6) U45.81(VDD_7) U45.93(VDD_8) U69.5(VCC) U73.8(VCC) ; also on sheet 4 18 22 37 41
VCC3V3_MP_ALT: D17.2(Anode) R743.1 ; also on sheet 25
VCC3V3_MP_ALT_DET: R417.1 R743.2 U45.99(PD6)
VCC3V3_MP_AMC: D16.2(Anode) ; also on sheet 18
BMC_GPIOINT0_FPGA_1V8_EXP2_T: U45.58(PF4) ; also on sheet 22
BMC_GPIOINT1_FPGA_1V8_EXP3_T: U45.46(PF5) ; also on sheet 22
BMC_GPIOINT2_FPGA_1V8_EXP1_T: U45.43(PF6) ; also on sheet 22
BMC_GPIOINT3_FPGA_3V3_EXP4: U45.42(PF7) ; also on sheet 27
BMC_GPIOINT4_FPGA_3V3_EXP5: U45.59(PF3) ; also on sheet 27
BMC_I2C1_SCL: U45.34(PA6) ; also on sheet 4 40 41 45 47
BMC_I2C1_SDA: U45.35(PA7) ; also on sheet 4 40 41 45 47
BMC_SPI0_CLK_FPGA_3V3: U45.28(PA2/SSI0CLK) ; also on sheet 11 13 27
BMC_SPI0_CS0#_FPGA_3V3: R795.2 U45.29(PA3/SSI0Fss) ; also on sheet 27
BMC_SPI0_CS1#: U45.25(PC4) ; also on sheet 11
BMC_SPI0_CS2#: U45.24(PC5) ; also on sheet 13
BMC_SPI0_MISO_FPGA_3V3: R479.2 ; also on sheet 11 13 27
BMC_SPI0_MOSI_FPGA_3V3: R480.2 ; also on sheet 11 13 27
BMC_TRGRSTZ: U45.39(PJ2) ; also on sheet 22
CDCM1_PLL_LOCK_3V3_BMC: U45.18(PG1) ; also on sheet 11
CDCM2_PLL_LOCK_3V3_BMC: U45.37(PG6) ; also on sheet 13
CDCM_CLKRSTZ_3V3_BMC: U45.97(PD4) ; also on sheet 11 13
CP2105_MCU_U0RX: U73.2(B) ; also on sheet 8
DEBUG_LED_BUFF_OE: U45.22(PC7) ; also on sheet 27
DIP_SW_B0: R750.1 SW1.1 U45.86(PH0)
DIP_SW_B1: R747.1 SW1.2 U45.85(PH1)
DIP_SW_B2: R737.1 SW1.3 U45.84(PH2)
DIP_SW_B3: R367.1 SW1.4 U45.83(PH3)
DSP_I2CBUS_EN: U45.47(PF0) ; also on sheet 26
DSP_PMBUS_EN: U45.98(PD5) ; also on sheet 37
FPGA_RST#: R776.1 R786.1 ; also on sheet 27
FULL_RESETz: C361.1 CN10.1 R474.1 R481.2 U45.87(PJ1)
LCD_A0: R782.2 ; also on sheet 4
LCD_RSTz: U45.100(PD7) ; also on sheet 4
LM10011_EN: U45.23(PC6) ; also on sheet 35
MAIN_POWER_GOOD: R875.2 U45.11(PD1) ; also on sheet 37
MAIN_POWER_START: U45.10(PD0) ; also on sheet 37
MCU_BOOTSELECT: CN13.1 R478.1 U45.36(PG7)
MCU_JTAG_TCK: U45.80(PC0/TCK/SWCLK) ; also on sheet 4
MCU_JTAG_TDI: U45.78(PC2/TDI) ; also on sheet 4
MCU_JTAG_TDO: U45.77(PC3/TDO/SWO) ; also on sheet 4
MCU_JTAG_TMS: U45.79(PC1/TMS/SWDIO) ; also on sheet 4
MCU_PA0_U0RX: U45.26(PA0/U0Rx) U73.5(Y)
MCU_PA1_U0TX: U45.27(PA1/U0Tx) ; also on sheet 4 8
MCU_RESET_SWz: C296.1 C811.1 R358.1 R359.2 U69.1(A)
MCU_RESETz: U45.64(~{RST}) U69.4(Y)
MCU_SPI1_CLK: U45.74(PE0) ; also on sheet 4
MCU_SPI1_CS0z: U45.75(PE1) ; also on sheet 4
MCU_SPI1_MOSI: R418.2 ; also on sheet 4
MCU_SRSTN_R: C819.2 R739.2 U69.3(B) ; also on sheet 4
MCU_U0RX: U73.1(A) ; also on sheet 4
MCU_U1RX: R769.2 U45.66(PB0)
MCU_U1TX: TP96.1 U45.67(PB1)
MCU_UART0_Detect#: U73.6(~{A}/B) ; also on sheet 4
MCU_WAKEz: CN10.2 U45.50(~{WAKE})
MCUOSC0: C354.1 U45.48(OSC0) Y6.1
MCUOSC1: C355.2 U45.49(OSC1) Y6.2
MCUXOSC0: R469.1 U45.52(XOSC0)
MCUXOSC0_R: OSC2.3(OUT) R469.2
MMC_BLUE_LED: R360.1 U45.15(PH7)
MMC_ENABLE_N: R458.2 ; also on sheet 18
MMC_GA0: R419.1 R742.1 U45.92(PB4) ; also on sheet 18
MMC_GA1: R420.1 R741.1 U45.91(PB5) ; also on sheet 18
MMC_GA2: R421.1 R740.1 U45.90(PB6) ; also on sheet 18
MMC_GAPU: R740.2 R741.2 R742.2 U45.89(PB7)
MMC_PS_N0: R771.2 U45.63(PH5) ; also on sheet 18
MMC_RED_LED: R310.1 U45.62(PH6)
PCIECLK_MCU_PD: R453.2 ; also on sheet 4
PCIECLK_MUX_SEL: U45.76(PH4) ; also on sheet 4
PCIECLK_OE: R448.2 ; also on sheet 4
PHY_RSTz: U45.1(PE7) ; also on sheet 2
PMBUS_ALERT: R794.1 U45.40(PG5) ; also on sheet 6 34 35 37
PMBUS_CTL: U45.41(PG4) ; also on sheet 35 37
PW_SEQ_I2C_EN: U45.5(PE5) ; also on sheet 4
PW_SEQ_RSTz: U45.2(PE6) ; also on sheet 37
SMB_SCL_IPMBL: R755.1 U45.72(PB2/I2C0SCL) ; also on sheet 18
SMB_SDA_IPMBL: R767.1 U45.65(PB3/I2C0SDA) ; also on sheet 18
SOC_I2C_EN: U45.6(PE4) ; also on sheet 41
SOC_POWER_GOOD: U45.13(PD3) ; also on sheet 37
SOC_POWER_START: U45.12(PD2) ; also on sheet 37
SOC_UART0_TXD_3V3: R769.1 ; also on sheet 6 8
SW7-P1: R454.1 SW2.1
SW8-P1: R481.1 SW3.1
SW10-P1: R359.1 RST_MCU1.2
WARM_RESETz: C342.1 R449.1 R454.2 U45.14(PJ0)
N17867217: CN11.1 R772.1
N17867248: R791.2 U45.51(~{HIB})
N17867264: C357.1 C845.2 C867.2 U45.7(LDO) U45.38(VDDC_1) U45.88(VDDC_2)
N17867410: R458.1 U45.19(PG0)
N17867440: R418.1 U45.96(PE3)
N17867517: R448.1 U45.16(PG3)
N17867543: R480.1 U45.31(PA5/SSI0Tx)
N17867545: R479.1 U45.30(PA4/SSI0Rx)
N17867642: R453.1 U45.17(PG2)
N17868029: R782.1 U45.61(PF1)
N17871372: R751.2 SW1.8
N17871388: R746.2 SW1.7
N17871396: R727.2 SW1.6
N17871404: R404.2 SW1.5
N17871693: Q8.1(B) R360.2
N17871700: D3.2(ANODE) R305.1
N17871704: D3.1(CATHODE) Q5.3(C)
N17871708: D5.2(ANODE) R353.1
N17871714: D5.1(CATHODE) Q8.3(C)
N17871763: Q5.1(B) R310.2
N19374782: R726.1 U69.6(C)
N21484004: R776.2 U45.60(PF2)

Not connected (* = marked no-connect by the designer): SW2 SH1(PTH_1)* SH2(PTH_2)*; SW3 3(PTH_1)* 4(PTH_2)*; U45 53(XOSC1)* 70(NC_1)* 71(NC_2)* 73(NC_3)* 95(PE2)*; U73 3(~{Y})*

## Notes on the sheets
sheet 5
- BMC Processor (LM3S2D93), switches, DIPsw, UART Rx Mux, LEDs
- UART1
- From SOC UART0 TX
- UART0
- I2C0
- MCU SPI0
- I2C1
- AMC MMC
- ICDI
- MCU SPI0
  CS1~CS2
- SPI1 to
  LCD
- LCD
  Control
- NOR FLASH
- MCU SPI0
- SOC
  Bootmode GPIO
- Close to U6.1
- GPIO to
  PMBUS
- UART RX MUX
- RESET
- ECS-160-20-3X-TR
- Power for MCU
- Budget 150mA
- [Note]1.D3, D5 should be placed on edge of PCB.
        2.D6, D7 should be placed inside of PCB.
- Close to MCU
- Vf=0.35V @ If=2A
- Close to MCU
- Vf=0.35V @ If=2A
- LEDS
- SWITCHES
- Note:LED Color is RED
- 2012/09/12 ADD
- 2012/09/26 modify
- WAKE
- MCU_RESET
- Power RESET
- Attention
- CN10(2-3)
- Note:LED Color is BLUE
- [Note]RST_MCU1 should be placed inside of PCB
- Note:PUSH Buttons
   Color is BLACK
- Note:PUSH Buttons
   Color is RED
- Note:PUSH Buttons
   Color is BLACK
